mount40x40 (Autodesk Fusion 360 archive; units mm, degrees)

design "Untitled" references "Normal-sd-ext"
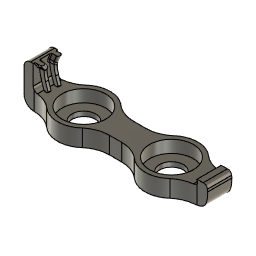
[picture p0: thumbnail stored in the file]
external_derived "ExternalDerived1"
sketch "Sketch1" plane through (0, 0, 0.1) normal (0, 0, -1) x axis (1, 0, 0)
  line L1 (45.2045, -32.4837) -> (44.2052, -32.4837)
  line L2 (45.2045, -31.8276) -> (45.2045, -32.4837)
  line L3 (44.2052, -31.8276) -> (45.2045, -31.8276)
  line L4 (44.2052, -32.4837) -> (44.2052, -31.8276)
  line L5 (44.4049, -31.8276) -> (44.7049, -31.8276)
  line L6 (44.4049, -32.4837) -> (44.4049, -31.8276)
  line L7 (44.7049, -32.4837) -> (44.4049, -32.4837)
  line L8 (44.7049, -31.8276) -> (44.7049, -32.4837)
  line L9 (45.0049, -32.4837) -> (44.4049, -32.4837)
  line L10 (45.0049, -31.8276) -> (45.0049, -32.4837)
  line L11 (44.4049, -31.8276) -> (45.0049, -31.8276)
  line L12 (44.4049, -32.4837) -> (44.4049, -31.8276)
  line L13 (44.4049, -34.1141) -> (44.7049, -34.1141)
  line L14 (44.4049, -34.7724) -> (44.4049, -34.1141)
  line L15 (44.7049, -34.7724) -> (44.4049, -34.7724)
  line L16 (44.7049, -34.1141) -> (44.7049, -34.7724)
  line L17 (44.2052, -34.1141) -> (45.2045, -34.1141)
  line L18 (45.0049, -34.7724) -> (44.4049, -34.7724)
  line L19 (45.0049, -34.1141) -> (45.0049, -34.7724)
  line L20 (44.4049, -34.1141) -> (45.0049, -34.1141)
  line L21 (44.4049, -34.7724) -> (44.4049, -34.1141)
  point P8 (44.4049, -32.4837)
  point P6 (44.7049, -31.8276)
  point P13 (44.7049, -34.1141)
  point P7 (44.4049, -31.8276)
  point P10 (45.0049, -32.4837)
  point P14 (44.4049, -34.1141)
  point P15 (44.4049, -34.7724)
  point P19 (45.0049, -34.7724)
  horizontal L5
  vertical L6
  horizontal L7
  vertical L8
  coincident L1 P8
  midpoint L3 P6
  horizontal L9
  vertical L10
  horizontal L11
  vertical L12
  horizontal L13
  vertical L14
  horizontal L15
  vertical L16
  midpoint P13 L17
  horizontal L18
  vertical L19
  horizontal L20
  vertical L21
  dimension "d1" distance P6 P7 = 0.3
  dimension "d2" distance P8 P10 = 0.6
  dimension "d3" distance P13 P14 = 0.3
  dimension "d4" distance P15 P19 = 0.6
extrude "Extrude1" add sketch "Sketch1" profile of L1 L3 L5 L6 L7 L8 L9 L10 L11 L12 L13 L14 L15 L16 L17 L18 L19 L20 L21 along normal blind 0.1 bodies "Body139", "Body140"
offset_faces "OffsetFaces1" distance -0.2
offset_faces "OffsetFaces2" distance -0.2
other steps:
derived_base_feature "Derived Base Feature" bodies "Body134", "Body139", "Body140"
named bodies: "Body134", "Body139", "Body140"

design "Normal-sd-ext"
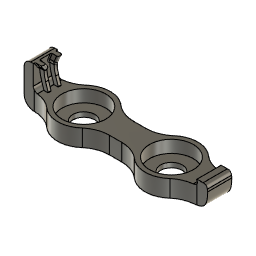
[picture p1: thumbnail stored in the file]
parameter "d260" = 1.4
parameter "d261" = 5
parameter "d262" = 10
parameter "d263" = 10
parameter "d264" = 10
parameter "d265" = 10
parameter "d266" = 10
parameter "d273" = 5
parameter "d274" = 5
parameter "d275" = 3
parameter "d277" = 5
parameter "d278" = 5
parameter "d279" = 0.5
parameter "d280" = -1
parameter "d281" = 0
parameter "d282" = -1
parameter "d283" = 0
parameter "d285" = 1
parameter "d287" = 15
parameter "d289" = 3.1
parameter "d290" = 1.4
parameter "d293" = 1.4
parameter "d295" = 2.5
parameter "d306" = 8
parameter "d311" = 1.25
parameter "d312" = 1.25
parameter "d325" = 0.2
parameter "d326" = 0
parameter "d327" = 0.2
parameter "d328" = 0
parameter "d329" = 1
parameter "d330" = 3
parameter "d331" = 1
parameter "d332" = 1
parameter "d333" = 3
parameter "d334" = 1
parameter "d335" = 0.5
parameter "d336" = 1
parameter "d337" = 0
parameter "d338" = 0
parameter "d339" = 0.2
parameter "d340" = 0
parameter "d341" = 0
parameter "d342" = 0
parameter "d354" = 4.5
parameter "d409" = 1.2
parameter "d418" = 2.25 (= "1.250 mm + 1 mm")
parameter "d419" = 1
parameter "d420" = 2.25 (= "1.25 mm + 1 mm")
parameter "d433" = 1
parameter "d434" = 1
parameter "d435" = 1
parameter "d436" = 1
parameter "d437" = 1
parameter "d442" = 14
parameter "d443" = 1
parameter "d453" = 0.29
parameter "d454" = 0
parameter "d455" = 0.4
parameter "d456" = 0
parameter "d457" = -5.71
parameter "d458" = 0
parameter "d459" = 1
parameter "d460" = 1
parameter "d461" = 1
parameter "d462" = 1
parameter "d463" = 1
parameter "d464" = 0
parameter "d465" = 0
parameter "d469" = 0.2
parameter "d470" = 1
parameter "d471" = 1
parameter "d472" = 0
parameter "d474" = 26.25
parameter "d476" = 0.25
parameter "d478" = 0.25
parameter "d479" = -0.5
parameter "d480" = 0
parameter "d481" = -0.5
parameter "d482" = 0
parameter "d483" = -0.5
parameter "d484" = 0
parameter "d485" = -0.5
parameter "d486" = 0
parameter "d487" = -1
parameter "d488" = 0
parameter "d489" = 1
parameter "d490" = 0
parameter "d491" = -1
parameter "d492" = 0
parameter "d493" = 1
parameter "d494" = 0
parameter "d495" = 0.5
parameter "d496" = 0
parameter "d497" = 0.5
parameter "d498" = 0
parameter "d499" = -0.5
parameter "d500" = 0
parameter "d501" = -0.5
parameter "d502" = 0
parameter "d503" = -0.5
parameter "d504" = 0
parameter "d505" = -0.5
parameter "d506" = 0
parameter "d507" = -1
parameter "d508" = 0
parameter "d509" = -1
parameter "d510" = 0
parameter "d511" = 1
parameter "d512" = 0
parameter "d513" = 1
parameter "d514" = 0
parameter "d515" = 0.5
parameter "d516" = 0
parameter "d517" = 0.5
parameter "d518" = 0
parameter "d519" = 0.5
parameter "d520" = 0
parameter "d521" = 0.5
parameter "d522" = 0
parameter "d523" = 1.8
parameter "d524" = 0
parameter "d525" = 2
parameter "d526" = 2.591
parameter "d527" = 18.5 (= "12.500 mm + 6 mm")
parameter "d528" = 10.25 (= "4.250 mm + 6 mm")
parameter "d529" = 0
parameter "d530" = 0
parameter "d531" = 0.409
parameter "d532" = 0.409
parameter "d533" = 27.6 (= "21.600 mm + 6 mm")
parameter "d534" = 9.5 (= "3.500 mm + 6 mm")
parameter "d535" = 0
parameter "d536" = 0
parameter "d537" = 0.409
parameter "d538" = 0.409
parameter "d539" = 0
parameter "d540" = 0
parameter "d542" = 6.3
parameter "d544" = 1
parameter "d546" = 0.5
parameter "d548" = 0.5
parameter "d550" = 1
parameter "d552" = 1.5
parameter "d554" = 1.5
parameter "d556" = 0.5
parameter "d558" = 0.5
parameter "d560" = 0.5
parameter "d562" = 0.5
parameter "d563" = -0.5
parameter "d564" = 0
parameter "d565" = 0
parameter "d571" = 0.5
parameter "d576" = 0.401
parameter "d577" = 0.401
parameter "d578" = 0.2
parameter "d579" = 0
parameter "d580" = -0.2
parameter "d581" = 0
parameter "d582" = 1
parameter "d583" = 1
parameter "d584" = 1
parameter "d585" = 1
parameter "d586" = 1
parameter "d587" = 0
parameter "d588" = 0
parameter "d589" = 0
parameter "d590" = 2
parameter "d591" = 0
parameter "d592" = -3.7
parameter "d593" = 0
parameter "d594" = 0.401
parameter "d595" = 0
parameter "d596" = 0
parameter "d597" = 0.5
parameter "d598" = 0
parameter "d599" = -8
parameter "d600" = 0
parameter "d601" = -0.5
parameter "d602" = 0
parameter "d603" = -0.5
parameter "d604" = 0
parameter "d606" = 0.2
parameter "d608" = 2
parameter "d610" = 1
parameter "d612" = 0.6
parameter "d613" = -0.7
parameter "d614" = 0
parameter "d616" = 1
parameter "d617" = 7.9 (= "8.30 mm - 0.4 mm")
parameter "d618" = 0
parameter "d619" = -0.2
parameter "d620" = 0
parameter "d621" = 1
parameter "d624" = 10
parameter "d625" = 0
parameter "d626" = 0
parameter "d627" = 0
parameter "d628" = 0.5
parameter "d629" = 0
parameter "d630" = 0.5
parameter "d631" = 0
parameter "d633" = 0.45
parameter "d635" = 0.5
parameter "d637" = 0.5
parameter "d643" = 0.5
parameter "d645" = 0.5
parameter "d647" = 0.5
parameter "d649" = 0.4
parameter "d651" = 0.5
parameter "d652" = 0.4
parameter "d653" = 0
named bodies: "Body", "Cover"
